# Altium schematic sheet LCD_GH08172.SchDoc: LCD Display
size A4; Date: 01-DEC-2013; Author: A.B; CompanyName: STMicroelectronics; Organization: Microcontrollers Division; Address1: 12, Rue Jules HOROWITZ; Address2: 38019 Grenoble; Address3: FRANCE; DocumentNumber: MB1184; Revision: C-01; SheetNumber: 6; SheetTotal: 10; Project: STM32L476G-DISCO
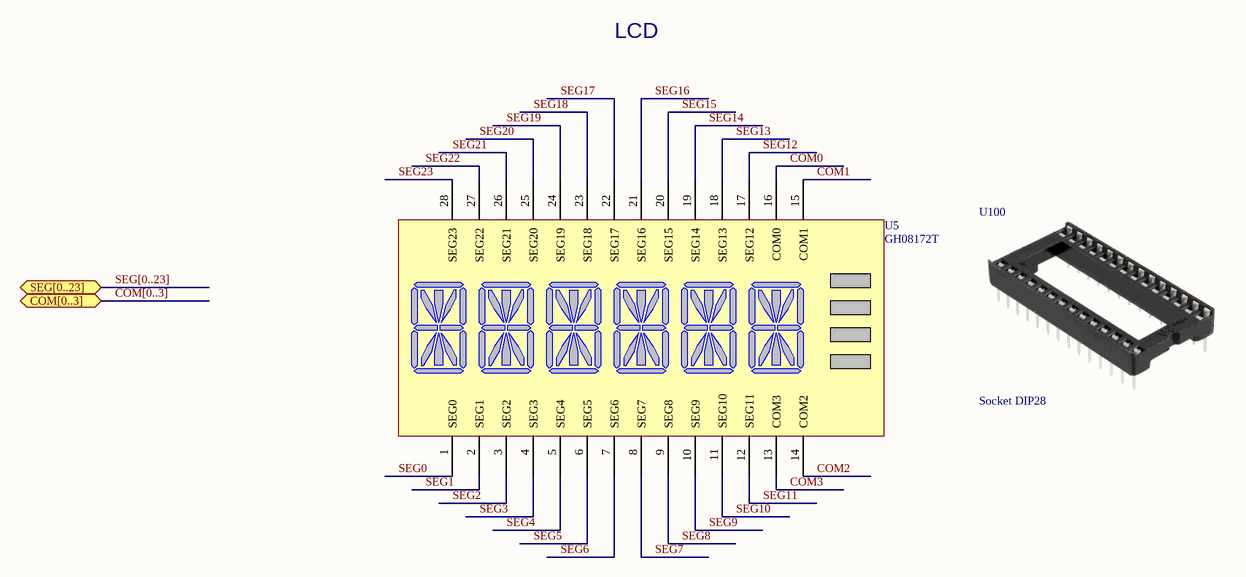
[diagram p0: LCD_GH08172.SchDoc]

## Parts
U5  GH08172T  [DIP28]
U100  Socket DIP28  [DIP28]

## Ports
COM[0..3], SEG[0..23]

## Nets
COM0: U5.16(COM0)
COM1: U5.15(COM1)
COM2: U5.14(COM2)
COM3: U5.13(COM3)
SEG0: U5.1(SEG0)
SEG1: U5.2(SEG1)
SEG2: U5.3(SEG2)
SEG3: U5.4(SEG3)
SEG4: U5.5(SEG4)
SEG5: U5.6(SEG5)
SEG6: U5.7(SEG6)
SEG7: U5.8(SEG7)
SEG8: U5.9(SEG8)
SEG9: U5.10(SEG9)
SEG10: U5.11(SEG10)
SEG11: U5.12(SEG11)
SEG12: U5.17(SEG12)
SEG13: U5.18(SEG13)
SEG14: U5.19(SEG14)
SEG15: U5.20(SEG15)
SEG16: U5.21(SEG16)
SEG17: U5.22(SEG17)
SEG18: U5.23(SEG18)
SEG19: U5.24(SEG19)
SEG20: U5.25(SEG20)
SEG21: U5.26(SEG21)
SEG22: U5.27(SEG22)
SEG23: U5.28(SEG23)

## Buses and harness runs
bus COM[0..3] = port COM[0..3]
bus SEG[0..23] = port SEG[0..23]

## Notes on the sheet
- LCD

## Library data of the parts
U5 = GH08172T: LCD 6x16 segments, 4 Common, Multiplexed 1/4 Duty, 1/3 Bias, 3V, DIP28; Manuf_1: hzdslcd; Order: GH08172T-B; ECCN_US/EU: EAR99/NEC
U100 = GH08172T_Socket: Socket DIP28 for GH08172T LCD; Manuf_Part_1: ED28DT; Manuf_1: On Shore Technology Inc; Order: ED3052-5-ND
